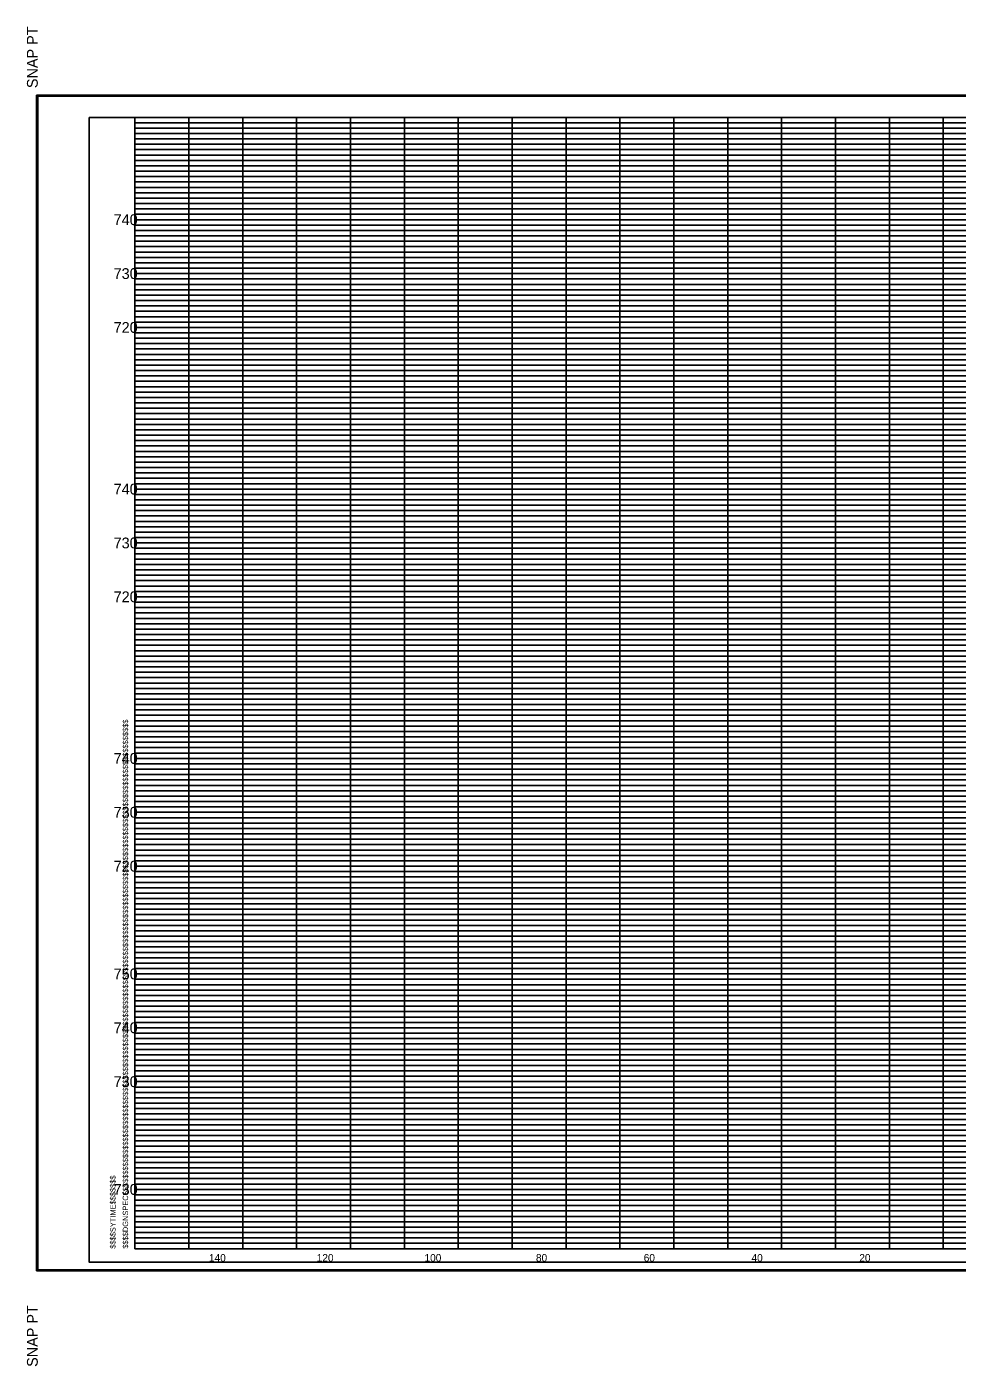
# Model space of a CAD drawing. Extents: x -200 to 1324, y -325 to 1497.
# Drawn here: x 979.9 to 1152.6, y 978.2 to 1226.8 of the extents above; entities that cross this region are included whole.
import ezdxf

# ---------------------------------------------------------------- set-up
doc = ezdxf.new("R2010")
doc.units = 0
for name, color, linetype in [('DESIGN - SHEET - Corner Text', 7, 'Continuous'), ('DESIGN - SHEET - Light Grid', 7, 'Continuous'), ('DESIGN - SHEET - Linework', 7, 'Continuous'), ('DESIGN - SHEET - Plot Shape', 7, 'Continuous'), ('DESIGN - TYPICAL - Text', 7, 'Continuous')]:
    doc.layers.add(name, color=color, linetype=linetype)

msp = doc.modelspace()

# ---------------------------------------------------------------- linework, layer by layer
at = {"layer": 'DESIGN - SHEET - Light Grid'}
for p, q in [((1000, 1209), (1080, 1209)), ((1080, 1209), (1160, 1209)), ((1000, 1208), (1080, 1208)), ((1000, 1207), (1080, 1207)), ((1000, 1206), (1080, 1206)), ((1080, 1208), (1160, 1208)), ((1080, 1207), (1160, 1207)), ((1080, 1206), (1160, 1206)), ((1000, 1205), (1080, 1205)), ((1000, 1204), (1080, 1204)), ((1080, 1205), (1160, 1205)), ((1080, 1204), (1160, 1204)), ((1000, 1203), (1080, 1203)), ((1000, 1202), (1080, 1202)), ((1000, 1201), (1080, 1201)), ((1080, 1203), (1160, 1203)), ((1080, 1202), (1160, 1202)), ((1080, 1201), (1160, 1201)), ((1000, 1199), (1080, 1199)), ((1080, 1199), (1160, 1199)), ((1000, 1198), (1080, 1198)), ((1000, 1197), (1080, 1197)), ((1000, 1196), (1080, 1196)), ((1080, 1198), (1160, 1198)), ((1080, 1197), (1160, 1197)), ((1080, 1196), (1160, 1196)), ((1000, 1195), (1080, 1195)), ((1000, 1194), (1080, 1194)), ((1080, 1195), (1160, 1195)), ((1080, 1194), (1160, 1194)), ((1000, 1193), (1080, 1193)), ((1000, 1192), (1080, 1192)), ((1000, 1191), (1080, 1191)), ((1080, 1193), (1160, 1193)), ((1080, 1192), (1160, 1192)), ((1080, 1191), (1160, 1191)), ((1000, 1189), (1080, 1189)), ((1080, 1189), (1160, 1189)), ((1000, 1188), (1080, 1188)), ((1000, 1187), (1080, 1187)), ((1000, 1186), (1080, 1186)), ((1080, 1188), (1160, 1188)), ((1080, 1187), (1160, 1187)), ((1080, 1186), (1160, 1186)), ((1000, 1185), (1080, 1185)), ((1000, 1184), (1080, 1184)), ((1080, 1185), (1160, 1185)), ((1080, 1184), (1160, 1184)), ((1000, 1183), (1080, 1183)), ((1000, 1182), (1080, 1182)), ((1000, 1181), (1080, 1181)), ((1080, 1183), (1160, 1183)), ((1080, 1182), (1160, 1182)), ((1080, 1181), (1160, 1181)), ((1000, 1179), (1080, 1179)), ((1080, 1179), (1160, 1179)), ((1000, 1178), (1080, 1178)), ((1000, 1177), (1080, 1177)), ((1080, 1178), (1160, 1178)), ((1080, 1177), (1160, 1177)), ((1000, 1176), (1080, 1176)), ((1000, 1175), (1080, 1175)), ((1000, 1174), (1080, 1174)), ((1080, 1176), (1160, 1176)), ((1080, 1175), (1160, 1175)), ((1080, 1174), (1160, 1174)), ((1000, 1173), (1080, 1173)), ((1000, 1172), (1080, 1172)), ((1080, 1173), (1160, 1173)), ((1080, 1172), (1160, 1172)), ((1000, 1171), (1080, 1171)), ((1000, 1169), (1080, 1169)), ((1080, 1171), (1160, 1171)), ((1080, 1169), (1160, 1169)), ((1000, 1168), (1080, 1168)), ((1000, 1167), (1080, 1167)), ((1080, 1168), (1160, 1168)), ((1080, 1167), (1160, 1167)), ((1000, 1166), (1080, 1166)), ((1000, 1165), (1080, 1165)), ((1000, 1164), (1080, 1164)), ((1080, 1166), (1160, 1166)), ((1080, 1165), (1160, 1165)), ((1080, 1164), (1160, 1164)), ((1000, 1163), (1080, 1163)), ((1000, 1162), (1080, 1162)), ((1080, 1163), (1160, 1163)), ((1080, 1162), (1160, 1162)), ((1000, 1161), (1080, 1161)), ((1000, 1159), (1080, 1159)), ((1080, 1161), (1160, 1161)), ((1080, 1159), (1160, 1159)), ((1000, 1158), (1080, 1158)), ((1000, 1157), (1080, 1157)), ((1080, 1158), (1160, 1158)), ((1080, 1157), (1160, 1157)), ((1000, 1156), (1080, 1156)), ((1000, 1155), (1080, 1155)), ((1000, 1154), (1080, 1154)), ((1080, 1156), (1160, 1156)), ((1080, 1155), (1160, 1155)), ((1080, 1154), (1160, 1154)), ((1000, 1153), (1080, 1153)), ((1000, 1152), (1080, 1152)), ((1080, 1153), (1160, 1153)), ((1080, 1152), (1160, 1152)), ((1000, 1151), (1080, 1151)), ((1000, 1149), (1080, 1149)), ((1080, 1151), (1160, 1151)), ((1080, 1149), (1160, 1149)), ((1000, 1148), (1080, 1148)), ((1000, 1147), (1080, 1147)), ((1080, 1148), (1160, 1148)), ((1080, 1147), (1160, 1147)), ((1000, 1146), (1080, 1146)), ((1000, 1145), (1080, 1145)), ((1000, 1144), (1080, 1144)), ((1080, 1146), (1160, 1146)), ((1080, 1145), (1160, 1145)), ((1080, 1144), (1160, 1144)), ((1000, 1143), (1080, 1143)), ((1000, 1142), (1080, 1142)), ((1080, 1143), (1160, 1143)), ((1080, 1142), (1160, 1142)), ((1000, 1141), (1080, 1141)), ((1000, 1139), (1080, 1139)), ((1080, 1141), (1160, 1141)), ((1080, 1139), (1160, 1139)), ((1000, 1138), (1080, 1138)), ((1000, 1137), (1080, 1137)), ((1080, 1138), (1160, 1138)), ((1080, 1137), (1160, 1137)), ((1000, 1136), (1080, 1136)), ((1000, 1135), (1080, 1135)), ((1000, 1134), (1080, 1134)), ((1080, 1136), (1160, 1136)), ((1080, 1135), (1160, 1135)), ((1080, 1134), (1160, 1134)), ((1000, 1133), (1080, 1133)), ((1000, 1132), (1080, 1132)), ((1080, 1133), (1160, 1133)), ((1080, 1132), (1160, 1132)), ((1000, 1131), (1080, 1131)), ((1000, 1129), (1080, 1129)), ((1080, 1131), (1160, 1131)), ((1080, 1129), (1160, 1129)), ((1000, 1128), (1080, 1128)), ((1000, 1127), (1080, 1127)), ((1080, 1128), (1160, 1128)), ((1080, 1127), (1160, 1127)), ((1000, 1126), (1080, 1126)), ((1000, 1125), (1080, 1125)), ((1000, 1124), (1080, 1124)), ((1080, 1126), (1160, 1126)), ((1080, 1125), (1160, 1125)), ((1080, 1124), (1160, 1124)), ((1000, 1123), (1080, 1123)), ((1000, 1122), (1080, 1122)), ((1080, 1123), (1160, 1123)), ((1080, 1122), (1160, 1122)), ((1000, 1121), (1080, 1121)), ((1000, 1119), (1080, 1119)), ((1080, 1121), (1160, 1121)), ((1080, 1119), (1160, 1119)), ((1000, 1118), (1080, 1118)), ((1000, 1117), (1080, 1117)), ((1080, 1118), (1160, 1118)), ((1080, 1117), (1160, 1117)), ((1000, 1116), (1080, 1116)), ((1000, 1115), (1080, 1115)), ((1000, 1114), (1080, 1114)), ((1080, 1116), (1160, 1116)), ((1080, 1115), (1160, 1115)), ((1080, 1114), (1160, 1114)), ((1000, 1113), (1080, 1113)), ((1000, 1112), (1080, 1112)), ((1080, 1113), (1160, 1113)), ((1080, 1112), (1160, 1112)), ((1000, 1111), (1080, 1111)), ((1000, 1109), (1080, 1109)), ((1080, 1111), (1160, 1111)), ((1080, 1109), (1160, 1109)), ((1000, 1108), (1080, 1108)), ((1000, 1107), (1080, 1107)), ((1080, 1108), (1160, 1108)), ((1080, 1107), (1160, 1107)), ((1000, 1106), (1080, 1106)), ((1000, 1105), (1080, 1105)), ((1000, 1104), (1080, 1104)), ((1080, 1106), (1160, 1106)), ((1080, 1105), (1160, 1105)), ((1080, 1104), (1160, 1104)), ((1000, 1103), (1080, 1103)), ((1000, 1102), (1080, 1102)), ((1080, 1103), (1160, 1103)), ((1080, 1102), (1160, 1102)), ((1000, 1101), (1080, 1101)), ((1000, 1099), (1080, 1099)), ((1080, 1101), (1160, 1101)), ((1080, 1099), (1160, 1099)), ((1000, 1098), (1080, 1098)), ((1000, 1097), (1080, 1097)), ((1080, 1098), (1160, 1098)), ((1080, 1097), (1160, 1097)), ((1000, 1096), (1080, 1096)), ((1000, 1095), (1080, 1095)), ((1000, 1094), (1080, 1094)), ((1080, 1096), (1160, 1096)), ((1080, 1095), (1160, 1095)), ((1080, 1094), (1160, 1094)), ((1000, 1093), (1080, 1093)), ((1000, 1092), (1080, 1092)), ((1080, 1093), (1160, 1093)), ((1080, 1092), (1160, 1092)), ((1000, 1091), (1080, 1091)), ((1000, 1089), (1080, 1089)), ((1080, 1091), (1160, 1091)), ((1080, 1089), (1160, 1089)), ((1000, 1088), (1080, 1088)), ((1000, 1087), (1080, 1087)), ((1080, 1088), (1160, 1088)), ((1080, 1087), (1160, 1087)), ((1000, 1086), (1080, 1086)), ((1000, 1085), (1080, 1085)), ((1080, 1086), (1160, 1086)), ((1080, 1085), (1160, 1085)), ((1000, 1084), (1080, 1084)), ((1000, 1083), (1080, 1083)), ((1000, 1082), (1080, 1082)), ((1080, 1084), (1160, 1084)), ((1080, 1083), (1160, 1083)), ((1080, 1082), (1160, 1082)), ((1000, 1081), (1080, 1081)), ((1080, 1081), (1160, 1081)), ((1000, 1079), (1080, 1079)), ((1000, 1078), (1080, 1078)), ((1000, 1077), (1080, 1077)), ((1080, 1079), (1160, 1079)), ((1080, 1078), (1160, 1078)), ((1080, 1077), (1160, 1077)), ((1000, 1076), (1080, 1076)), ((1000, 1075), (1080, 1075)), ((1080, 1076), (1160, 1076)), ((1080, 1075), (1160, 1075)), ((1000, 1074), (1080, 1074)), ((1000, 1073), (1080, 1073)), ((1000, 1072), (1080, 1072)), ((1080, 1074), (1160, 1074)), ((1080, 1073), (1160, 1073)), ((1080, 1072), (1160, 1072)), ((1000, 1071), (1080, 1071)), ((1080, 1071), (1160, 1071)), ((1000, 1069), (1080, 1069)), ((1000, 1068), (1080, 1068)), ((1000, 1067), (1080, 1067)), ((1080, 1069), (1160, 1069)), ((1080, 1068), (1160, 1068)), ((1080, 1067), (1160, 1067)), ((1000, 1066), (1080, 1066)), ((1000, 1065), (1080, 1065)), ((1080, 1066), (1160, 1066)), ((1080, 1065), (1160, 1065)), ((1000, 1064), (1080, 1064)), ((1000, 1063), (1080, 1063)), ((1000, 1062), (1080, 1062)), ((1080, 1064), (1160, 1064)), ((1080, 1063), (1160, 1063)), ((1080, 1062), (1160, 1062)), ((1000, 1061), (1080, 1061)), ((1080, 1061), (1160, 1061)), ((1000, 1059), (1080, 1059)), ((1000, 1058), (1080, 1058)), ((1000, 1057), (1080, 1057)), ((1080, 1059), (1160, 1059)), ((1080, 1058), (1160, 1058)), ((1080, 1057), (1160, 1057)), ((1000, 1056), (1080, 1056)), ((1000, 1055), (1080, 1055)), ((1080, 1056), (1160, 1056)), ((1080, 1055), (1160, 1055)), ((1000, 1054), (1080, 1054)), ((1000, 1053), (1080, 1053)), ((1000, 1052), (1080, 1052)), ((1080, 1054), (1160, 1054)), ((1080, 1053), (1160, 1053)), ((1080, 1052), (1160, 1052)), ((1000, 1051), (1080, 1051)), ((1080, 1051), (1160, 1051)), ((1000, 1049), (1080, 1049)), ((1000, 1048), (1080, 1048)), ((1000, 1047), (1080, 1047)), ((1080, 1049), (1160, 1049)), ((1080, 1048), (1160, 1048)), ((1080, 1047), (1160, 1047)), ((1000, 1046), (1080, 1046)), ((1000, 1045), (1080, 1045)), ((1080, 1046), (1160, 1046)), ((1080, 1045), (1160, 1045)), ((1000, 1044), (1080, 1044)), ((1000, 1043), (1080, 1043)), ((1000, 1042), (1080, 1042)), ((1080, 1044), (1160, 1044)), ((1080, 1043), (1160, 1043)), ((1080, 1042), (1160, 1042)), ((1000, 1041), (1080, 1041)), ((1080, 1041), (1160, 1041)), ((1000, 1039), (1080, 1039)), ((1000, 1038), (1080, 1038)), ((1000, 1037), (1080, 1037)), ((1080, 1039), (1160, 1039)), ((1080, 1038), (1160, 1038)), ((1080, 1037), (1160, 1037)), ((1000, 1036), (1080, 1036)), ((1000, 1035), (1080, 1035)), ((1080, 1036), (1160, 1036)), ((1080, 1035), (1160, 1035)), ((1000, 1034), (1080, 1034)), ((1000, 1033), (1080, 1033)), ((1000, 1032), (1080, 1032)), ((1080, 1034), (1160, 1034)), ((1080, 1033), (1160, 1033)), ((1080, 1032), (1160, 1032)), ((1000, 1031), (1080, 1031)), ((1080, 1031), (1160, 1031)), ((1000, 1029), (1080, 1029)), ((1000, 1028), (1080, 1028)), ((1000, 1027), (1080, 1027)), ((1080, 1029), (1160, 1029)), ((1080, 1028), (1160, 1028)), ((1080, 1027), (1160, 1027)), ((1000, 1026), (1080, 1026)), ((1000, 1025), (1080, 1025)), ((1080, 1026), (1160, 1026)), ((1080, 1025), (1160, 1025)), ((1000, 1024), (1080, 1024)), ((1000, 1023), (1080, 1023)), ((1000, 1022), (1080, 1022)), ((1080, 1024), (1160, 1024)), ((1080, 1023), (1160, 1023)), ((1080, 1022), (1160, 1022)), ((1000, 1021), (1080, 1021)), ((1080, 1021), (1160, 1021)), ((1000, 1019), (1080, 1019)), ((1000, 1018), (1080, 1018)), ((1000, 1017), (1080, 1017)), ((1080, 1019), (1160, 1019)), ((1080, 1018), (1160, 1018)), ((1080, 1017), (1160, 1017)), ((1000, 1016), (1080, 1016)), ((1000, 1015), (1080, 1015)), ((1080, 1016), (1160, 1016)), ((1080, 1015), (1160, 1015)), ((1000, 1014), (1080, 1014)), ((1000, 1013), (1080, 1013)), ((1000, 1012), (1080, 1012)), ((1080, 1014), (1160, 1014)), ((1080, 1013), (1160, 1013)), ((1080, 1012), (1160, 1012)), ((1000, 1011), (1080, 1011)), ((1080, 1011), (1160, 1011)), ((1000, 1009), (1080, 1009)), ((1000, 1008), (1080, 1008)), ((1000, 1007), (1080, 1007)), ((1080, 1009), (1160, 1009)), ((1080, 1008), (1160, 1008)), ((1080, 1007), (1160, 1007)), ((1000, 1006), (1080, 1006)), ((1000, 1005), (1080, 1005)), ((1080, 1006), (1160, 1006)), ((1080, 1005), (1160, 1005)), ((1000, 1004), (1080, 1004)), ((1000, 1003), (1080, 1003)), ((1000, 1002), (1080, 1002)), ((1080, 1004), (1160, 1004)), ((1080, 1003), (1160, 1003)), ((1080, 1002), (1160, 1002)), ((1000, 1001), (1080, 1001)), ((1080, 1001), (1160, 1001))]:
    msp.add_line(p, q, dxfattribs=at)
at = {"layer": 'DESIGN - SHEET - Linework'}
for p, q in [((981.77, 995.86), (981.77, 1214.14)), ((981.77, 1214.14), (1322.17, 1214.14)), ((1010, 1000), (1010, 1210)), ((1020, 1000), (1020, 1210)), ((1030, 1000), (1030, 1210)), ((1040, 1000), (1040, 1210)), ((1050, 1000), (1050, 1210)), ((1060, 1000), (1060, 1210)), ((1070, 1000), (1070, 1210)), ((1080, 1000), (1080, 1210)), ((1090, 1000), (1090, 1210)), ((1100, 1000), (1100, 1210)), ((1110, 1000), (1110, 1210)), ((1120, 1000), (1120, 1210)), ((1130, 1000), (1130, 1210)), ((1140, 1000), (1140, 1210)), ((1150, 1000), (1150, 1210)), ((1000, 1200), (1280, 1200)), ((1000, 1190), (1320, 1190)), ((1000, 1180), (1320, 1180)), ((1000, 1170), (1320, 1170)), ((1000, 1160), (1320, 1160)), ((1000, 1150), (1320, 1150)), ((1000, 1140), (1320, 1140)), ((1000, 1130), (1320, 1130)), ((1000, 1120), (1320, 1120)), ((1000, 1110), (1320, 1110)), ((1000, 1100), (1320, 1100)), ((1000, 1090), (1320, 1090)), ((1000, 1080), (1320, 1080)), ((1000, 1070), (1320, 1070)), ((1000, 1060), (1320, 1060)), ((1000, 1050), (1320, 1050)), ((1000, 1040), (1320, 1040)), ((1000, 1030), (1320, 1030)), ((1000, 1020), (1320, 1020)), ((1000, 1010), (1320, 1010)), ((981.77, 995.86), (1322.17, 995.86))]:
    msp.add_line(p, q, dxfattribs=at)
msp.add_lwpolyline([(1000, 1210), (1000, 1000), (1320, 1000), (1320, 1210), (1000, 1210)], dxfattribs=at)
at = {"layer": 'DESIGN - SHEET - Plot Shape'}
for points in [[(981.97, 1213.94), (1321.97, 1213.94), (1321.97, 996.06), (981.97, 996.06)], [(991.5, 1210), (1320, 1210), (1320, 997.5), (991.5, 997.5)]]:
    msp.add_lwpolyline(points, close=True, dxfattribs=at)

# ---------------------------------------------------------------- texts
at = {"layer": 'DESIGN - SHEET - Corner Text'}
for s, height, p in [('  SNAP PT', 2, (981.97, 1213.94)), ('$$$$DGNSPEC$$$$$$$$$$$$$$$$$$$$$$$$$$$$$$$$$$$$$$$$$$$$$$$$$$$$$$$$$$$$$$$$$$$$$$$$$$$$$$$$$$$$$$$$$$$$$$$$$$$$$$$$$$$$$$$$$$$', 1.00002, (998.74, 1000)), ('$$$$SYTIME$$$$$$$', 1, (996.42, 1000)), ('SNAP PT  ', 2, (981.97, 978.06))]:
    msp.add_text(s, height=height, rotation=90, dxfattribs=at).set_placement(p)
at = {"layer": 'DESIGN - TYPICAL - Text'}
for s, height, p in [('     740     ', 2, (992.34, 1190)), ('     730     ', 2, (992.34, 1180)), ('     720     ', 2, (992.34, 1170)), ('     740     ', 2, (992.34, 1140)), ('     730     ', 2, (992.34, 1130)), ('     720     ', 2, (992.34, 1120)), ('     740     ', 2, (992.34, 1090)), ('     730     ', 2, (992.34, 1080)), ('     720     ', 2, (992.34, 1070)), ('     750     ', 2, (992.34, 1050)), ('     740     ', 2, (992.34, 1040)), ('     730     ', 2, (992.34, 1030)), ('     730     ', 2, (992.34, 1010)), ('     140     ', 1.4, (1011.14, 997.6)), ('     120     ', 1.4, (1031.14, 997.6)), ('     100     ', 1.4, (1051.14, 997.6)), ('     80     ', 1.4, (1071.82, 997.6)), ('     60     ', 1.4, (1091.82, 997.6)), ('     40     ', 1.4, (1111.82, 997.6)), ('     20     ', 1.4, (1131.82, 997.6))]:
    msp.add_text(s, height=height, dxfattribs=at).set_placement(p)

doc.saveas('drawing.dxf')
